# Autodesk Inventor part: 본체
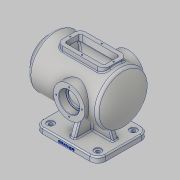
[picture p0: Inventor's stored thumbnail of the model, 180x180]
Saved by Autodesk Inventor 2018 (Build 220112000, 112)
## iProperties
Created: 2021-11
Part Number: 본체
Material: 알루미늄 6061
Document SubType Name: Modeling
Designer: home
Density: 2.7 g/cm^3
Appearance: 알루미늄 - 평지
Mass: 3539.14 g
Surface Area: 2407.45 cm^2
Volume: 1310.79 cm^3
Author: home
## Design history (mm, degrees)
sketch "스케치1"
  geometry: L1 (0, 0)-(210, 0); L2 (0, 32.5)-(0, 47.5); L3 (0, 47.5)-(10, 47.5); L4 (10, 47.5)-(10, 65); L5 (10, 65)-(185.993, 65); L6 (25, 55)-(181.239, 55); L7 (25, 32.5)-(25, 55); L8 (0, 32.5)-(25, 32.5); L9 (200, 0)-(210, 0); A1 r 100 centre (110, 0) between (210, 0) and (185.993, 65); A2 r 90 centre (110, 0) between (200, 0) and (181.239, 55)
  constraints: 18 end point, 5 perpendicular, 4 point on circle, 2 centre point, 1 horizontal, 1 horizontal alignment, 1 parallel, 1 tangent, 1 vertical
  dimensions: "d1" = 210 distance of L1.start L1.end; "d2" = 95 diameter of L3 L1; "d3" = 130 diameter of L5 L1; "d4" = 10 distance of L2.end L3.end; "d5" = 10 radial gap between concentric circles of A1 A2; "d6" = 10 distance between parallel lines of L5 L6; "d7" = 25 distance between parallel lines of L7 L2; "d8" = 65 diameter of L8 L1; "d9" = 90 radius of A2; "d10" = 65 distance from line of L9.start L5
revolve "회전1" sketch "스케치1" stored, may be unused: angle "d11" = 90 deg
node "작업 평면1"
sketch "스케치2"
  geometry: L1 (-30, 65)-(-190, 65); L2 (-190, 65)-(-190, -65); L3 (-190, -65)-(-30, -65); L4 (-30, -65)-(-30, 65); L5 (-30, 65)-(-190, -65); L6 (-190, 65)-(-30, -65); 3 further points
  constraints: 12 end point, 3 midpoint, 2 parallel, 1 horizontal, 1 horizontal alignment, 1 perpendicular
  dimensions: "d13" = 130 distance of L1.end L2.end; "d14" = 160 distance of L1.start L1.end; "d15" = 30 distance from line of point (0, 0) L4
extrude "돌출1" join sketch "스케치2" distance "d16" = 14; taper "d17" = 0 deg
node "작업 평면2"
sketch "스케치4"
  geometry: L1 (0, 14)-(130, 14) reference; L2 (65, 49)-(65, 14); L3 (115, 14)-(98.809, 58.485); L4 (115, 14)-(65, 14); A1 r 65 centre (65, 114) between (65, 49) and (98.809, 58.485); 1 further point
  constraints: 6 end point, 2 point on circle, 1 centre point, 1 coincident, 1 horizontal, 1 midpoint, 1 point on line, 1 vertical
  dimensions: "d22" = 50 distance of L2.end L3.start; "d23" = 110 deg angle of L1 L3; "d24" = 65 radius of A1
extrude "돌출2" join sketch "스케치4" stored distance "d25" = 14; taper "d26" = 0 deg
sketch "스케치5"
  geometry: L1 (190, -100)-(30, -100) reference; L2 (10, -65)-(185.993, -65) reference; L3 (170, -100)-(157.261, -65); L4 (110, -149.8)-(110, 100.8) reference; 1 further point
  constraints: 2 end point, 2 point on line
  dimensions: "d28" = 110 deg angle of L1 L3; "d29" = 60 distance from line of L4 L3.start
feature "리브1" sketch "스케치5" dims "d30" = 1, "d31" = 14, "d32" = 0, "d33" = 0, "d34" = 1, "d35" = 1
node "작업 평면3"
sketch "스케치8"
  geometry: L1 (0, -47.5)-(0, 47.5) reference; C1 r 40 at (127, 0); 1 further point
  constraints: 1 centre point, 1 horizontal alignment
  dimensions: "d41" = 80 diameter of C1; "d42" = 127 distance from line of C1.centre L1
extrude "돌출3" join sketch "스케치8" stored distance "d43" = 14; taper "d44" = 0 deg
sketch "스케치9"
  geometry: C1 r 26 at (0, 0); 1 further point
  constraints: 1 centre point, 1 horizontal alignment
  dimensions: "d45" = 52 diameter of C1; "d46" = 127 distance of point (-127, 0) C1.centre
extrude "돌출4" cut sketch "스케치9" distance "d47" = 18; taper "d48" = 0 deg
sketch "스케치10"
  geometry: C1 r 21 at (0, 0); 1 further point
  constraints: 1 centre point, 1 horizontal alignment
  dimensions: "d49" = 42 diameter of C1; "d50" = 127 distance of point (-127, 0) C1.centre
extrude "돌출5" cut sketch "스케치10" stored distance "d51" = 18; taper "d52" = 0 deg
node "작업 평면4"
sketch "스케치11"
  geometry: L1 (-50, 30)-(-170, 30); L2 (-170, 30)-(-170, -30); L3 (-170, -30)-(-50, -30); L4 (-50, -30)-(-50, 30); L5 (-50, 30)-(-170, -30); L6 (-170, 30)-(-50, -30); L7 (0, 47.5)-(0, -47.5) reference; 3 further points
  constraints: 12 end point, 3 midpoint, 2 parallel, 1 horizontal, 1 horizontal alignment, 1 perpendicular
  dimensions: "d54" = 60 distance of L1.end L2.end; "d55" = 120 distance of L2.end L3.end; "d56" = 50 distance between parallel lines of L7 L4
extrude "돌출6" join sketch "스케치11" stored distance "d57" = 18; taper "d58" = 0 deg
sketch "스케치12"
  geometry: L1 (170, 30)-(50, 30) reference; L2 (170, -30)-(170, 30) reference; L3 (50, -30)-(170, -30) reference; L4 (50, 30)-(50, -30) reference; L5 (60, 20)-(160, 20); L6 (160, 20)-(160, -20); L7 (160, -20)-(60, -20); L8 (60, -20)-(60, 20); 1 further point
  constraints: 8 end point, 3 other
  dimensions: "d59" = 10 distance between parallel lines of L1 L5
extrude "돌출7" cut sketch "스케치12" stored distance "d60" = 18; taper "d61" = 0 deg; dims "d7" = 25
sketch "스케치13" dims "d62" = 80
  geometry: C1 r 32.5 at (0, 0) reference; 3 further points
  constraints: 2 vertical alignment, 1 coincident, 2 other
hole "구멍1" sketch "스케치13" at (0, 40) diameter "d63" = 3.242; stored, may be unused: countersink angle "d67" = 90 deg, drill point angle "d69" = 118 deg; dims "d64" = 11, "d65" = 4, "d66" = 2, "d68" = 13
sketch "스케치14" dims "d73" = 65
  geometry: L1 (-127, -47.5)-(-127, 47.5) reference; 3 further points
  constraints: 2 vertical alignment, 1 horizontal alignment, 2 other
  dimensions: "d74" = 127 distance from line of L1 point (0, 0)
hole "구멍2" sketch "스케치14" at (0, 32.5) diameter "d75" = 3.242; stored, may be unused: countersink angle "d79" = 90 deg, drill point angle "d81" = 118 deg; dims "d76" = 11, "d77" = 4, "d78" = 2, "d80" = 13
sketch "스케치15"
  geometry: L1 (50, 30)-(50, -30) reference; L2 (170, -30)-(170, 30) reference; 5 further points
  constraints: 2 horizontal alignment
  dimensions: "d85" = 60 distance from line of L1 point (110, 25); "d86" = 60 distance from line of L1 point (110, -25); "d87" = 5 distance from line of L1 point (55, 0); "d88" = 5 distance from line of L2 point (165, 0); "d89" = 25 vertical distance of point (0, 0) point (110, 25); "d90" = 25 vertical distance of point (0, 0) point (110, -25)
hole "구멍3" sketch "스케치15" at (110, 25), (110, -25), (55, 0), (165, 0) diameter "d91" = 3.242; stored, may be unused: countersink angle "d95" = 90 deg, drill point angle "d97" = 118 deg; dims "d92" = 9, "d93" = 4, "d94" = 2, "d96" = 11
fillet "모깎기1" dims "d98" = 10, "d100" = 15, "d101" = 0.3, "d102" = 20
sketch "스케치16"
  geometry: L1 (190, -45)-(190, 45) reference; L2 (50, -65)-(170, -65) reference; L3 (30, 45)-(30, -45) reference; L4 (170, 65)-(50, 65) reference; C1 r 9 at (50, 45); C2 r 9 at (170, 45); C3 r 9 at (170, -45); C4 r 9 at (50, -45); A1 r 20 centre (50, 45) between (50, 65) and (30, 45) reference; A2 r 20 centre (170, 45) between (190, 45) and (170, 65) reference; A3 r 20 centre (170, -45) between (170, -65) and (190, -45) reference; A4 r 20 centre (50, -45) between (30, -45) and (50, -65) reference; A5 r 20 centre (50, 45) between (50, 65) and (30, 45) reference; 1 further point
  constraints: 4 centre point, 4 coincident, 3 equal radius
  dimensions: "d103" = 18 diameter of C1
extrude "돌출8" cut sketch "스케치16" distance "d104" = 2; taper "d105" = 0 deg
sketch "스케치17"
  geometry: L1 (140, 0)-(140, 90) reference; L2 (0, -20)-(120, -20) reference; L3 (-20, 90)-(-20, 0) reference; L4 (120, 110)-(0, 110) reference; C1 r 4.5 at (0, 90); C2 r 4.5 at (120, 90); C3 r 4.5 at (120, 0); C4 r 4.5 at (0, 0); A1 r 20 centre (120, 90) between (140, 90) and (120, 110) reference; A2 r 20 centre (120, 0) between (120, -20) and (140, 0) reference; A3 r 20 centre (0, 0) between (-20, 0) and (0, -20) reference; A4 r 20 centre (0, 90) between (0, 110) and (-20, 90) reference; 1 further point
  constraints: 4 centre point, 4 coincident, 3 equal radius
  dimensions: "d106" = 9 diameter of C1
extrude "돌출9" cut sketch "스케치17" extent not by distance; stored distance "d107" = 0; taper "d108" = 0 deg
chamfer "모따기1" distance "d110" = 1; stored, may be unused: second distance "d111" = 2, angle "d112" = 45 deg
fillet "모깎기3" dims "d113" = 3
fillet "모깎기4" dims "d124" = 5, "d125" = 3
sketch "스케치18"
  geometry: L1 (0, 0)-(120, 0) reference; L2 (-20, 14)-(-20, 0) reference; 3 further points
  constraints: 1 other
  dimensions: "d115" = 5 distance from line of L1 point (60, 5); "d116" = 80 distance from line of L2 point (60, 5)
feature "엠보싱1" sketch "스케치18" dims "d13" = 130, "d14" = 160, "d15" = 30, "d117" = 0.5, "d118" = 0
fillet "모깎기5" dims "d119" = 5, "d120" = 3
fillet "모깎기6" dims "d121" = 3
fillet "모깎기7" dims "d122" = 3
node "솔리드1"
mirror "미러1"
mirror "미러2"
mirror "미러3"
pattern_circular "원형 패턴1" dims angle "d71" = 360 deg
pattern_circular "원형 패턴2" dims angle "d83" = 360 deg
mirror "미러4"
node "투영된 루프1"
node "투영된 루프2"
other parameters: "d12" = -114, "d40" = 75
